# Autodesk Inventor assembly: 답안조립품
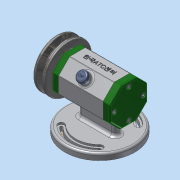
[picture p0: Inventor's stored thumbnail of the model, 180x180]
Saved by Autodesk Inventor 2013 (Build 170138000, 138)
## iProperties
Created: 2017-06
Part Number: 답안조립품
Document SubType Name: Assembly
Designer: dgall
Author: dgall
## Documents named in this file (14)
- C:\Users\dgall\Desktop\470607V1020\답안조립품.iam
- C:\Users\dgall\Desktop\470607V1020\본체.ipt
- C:\Users\dgall\Desktop\470607V1020\V벨트풀리.ipt
- C:\Users\dgall\Desktop\470607V1020\고무캡.ipt
- C:\Users\dgall\Desktop\470607V1020\뒤커버.ipt
- C:\Users\dgall\Desktop\470607V1020\베어링 15 x 32 x 9.ipt
- C:\Users\dgall\Desktop\470607V1020\스프링와셔 8.ipt
- C:\Users\dgall\Desktop\470607V1020\앞커버.ipt
- C:\Users\dgall\Desktop\470607V1020\오일 실 15 25 7.ipt
- C:\Users\dgall\Desktop\470607V1020\와셔 8x17.ipt
- C:\Users\dgall\Desktop\470607V1020\축.ipt
- C:\Users\dgall\Desktop\470607V1020\키 3 x 3 x 12.ipt
- C:\Users\dgall\Desktop\470607V1020\너트 M 8.ipt
- C:\Users\dgall\Desktop\470607V1020\볼트 M4 x 12.ipt
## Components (2 placed, 2 different names)
1. V벨트풀리:1 — 각도:2
2. 고무캡:1
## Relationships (1: Angle 1)
- 각도:2 [Angle]: V벨트풀리:1
